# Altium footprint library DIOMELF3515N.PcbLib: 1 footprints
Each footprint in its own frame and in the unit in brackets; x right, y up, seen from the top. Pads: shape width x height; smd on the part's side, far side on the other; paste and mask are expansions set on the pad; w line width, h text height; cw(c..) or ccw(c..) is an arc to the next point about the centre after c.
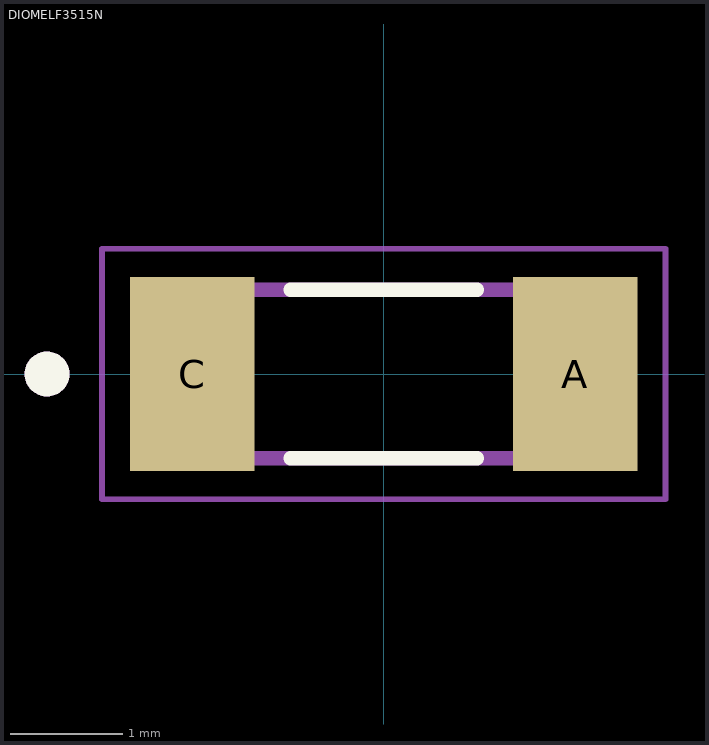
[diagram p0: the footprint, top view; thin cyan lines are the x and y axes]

## DIOMELF3515N [mm]
pads (2):
  rect 1.11x1.73 smd: A(1.705,0) C(-1.705,0)
Top Overlay:
  circle w0.2: c-3,0 r0.1
  lines w0.127: -0.83,-0.75 0.83,-0.75 ; -0.83,0.75 0.83,0.75
Mechanical 13:
  circle w0.2: c-3,0 r0.1
  lines w0.127: -1.75,-0.75 -1.75,0.75 1.75,0.75 1.75,-0.75 -1.75,-0.75
Mechanical 15:
  lines w0.05: -2.51,-1.115 -2.51,1.115 2.51,1.115 2.51,-1.115 -2.51,-1.115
